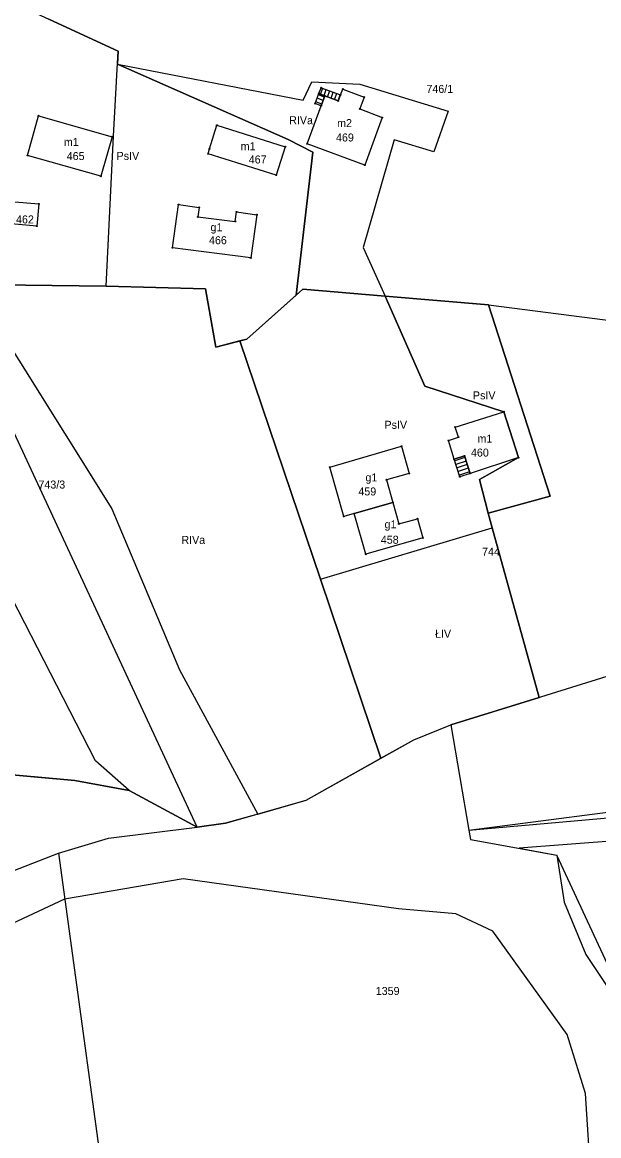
# Model space of a CAD drawing. Extents: x 7498273 to 7499989, y 5499795 to 5500810.
# Drawn here: x 7498588.9 to 7498697.1, y 5500193.5 to 5500402.3 of the extents above; entities that cross this region are included whole.
import ezdxf

# ---------------------------------------------------------------- set-up
doc = ezdxf.new("R2010")
doc.units = 0
for name, color, linetype in [('209-oznaczenie konturu klasyfikacyjnego', 7, 'Continuous'), ('211-numer działki ewidencyjnej', 7, 'Continuous'), ('217-kontur klasyfikacyjny', 7, 'Continuous'), ('218-kontur użytku gruntowego', 7, 'Continuous'), ('219-działka ewidencyjna', 7, 'Continuous'), ('312-budynek ewidencyjny', 7, 'Continuous'), ('312-oznaczenie budynku ewidencyjnego', 7, 'Continuous'), ('312-oznaczenie budynku ewidencyjnego-Atr117', 7, 'Continuous'), ('352-schody', 7, 'Continuous'), ('Punkt budynku', 7, 'Continuous')]:
    doc.layers.add(name, color=color, linetype=linetype)

# ---------------------------------------------------------------- blocks, each defined once
blk = doc.blocks.new('PUNKTBUD')
blk.add_circle((0, 0), 0.09)

msp = doc.modelspace()

# ---------------------------------------------------------------- linework, layer by layer
at = {"layer": '217-kontur klasyfikacyjny'}
for points in [[(7498606.9, 5500396.84), (7498593.88, 5500402.87)], [(7498606.76, 5500394.41), (7498606.9, 5500396.84)], [(7498638.84, 5500380.3), (7498606.76, 5500394.41)], [(7498606.76, 5500394.41), (7498641.62, 5500387.66)], [(7498641.62, 5500387.66), (7498643.28, 5500391.11)], [(7498643.28, 5500391.11), (7498652.24, 5500390.7)], [(7498652.24, 5500390.7), (7498668.87, 5500385.6)], [(7498668.87, 5500385.6), (7498666.18, 5500378.02)], [(7498643.47, 5500377.94), (7498638.84, 5500380.3)], [(7498658.73, 5500380.22), (7498652.9, 5500360.03)], [(7498666.18, 5500378.02), (7498658.73, 5500380.22)], [(7498640.34, 5500351.13), (7498643.47, 5500377.94)], [(7498652.9, 5500360.03), (7498657.01, 5500350.92)], [(7498579.32, 5500353.13), (7498604.68, 5500352.8)], [(7498579.32, 5500353.13), (7498605.75, 5500311.04)], [(7498604.68, 5500352.8), (7498623.33, 5500352.31)], [(7498623.33, 5500352.31), (7498625.26, 5500341.37)], [(7498631.03, 5500342.86), (7498640.34, 5500351.13)], [(7498640.34, 5500351.13), (7498641.57, 5500352.22)], [(7498641.57, 5500352.22), (7498657.01, 5500350.92)], [(7498657.01, 5500350.92), (7498676.4, 5500349.28)], [(7498664.46, 5500334.03), (7498657.01, 5500350.92)], [(7498676.4, 5500349.28), (7498687.99, 5500313.43)], [(7498625.26, 5500341.37), (7498629.74, 5500342.53)], [(7498629.74, 5500342.53), (7498631.03, 5500342.86)], [(7498644.86, 5500297.89), (7498629.74, 5500342.53)], [(7498679.3, 5500329.25), (7498664.46, 5500334.03)], [(7498682.05, 5500320.65), (7498679.3, 5500329.25)], [(7498674.7, 5500316.58), (7498682.05, 5500320.65)], [(7498676.35, 5500310.23), (7498674.7, 5500316.58)], [(7498687.99, 5500313.43), (7498676.35, 5500310.23)], [(7498605.75, 5500311.04), (7498618.44, 5500280.9)], [(7498676.35, 5500310.23), (7498677.12, 5500307.48)], [(7498644.86, 5500297.89), (7498677.12, 5500307.48)], [(7498677.12, 5500307.48), (7498685.92, 5500275.7)], [(7498656.24, 5500264.28), (7498644.86, 5500297.89)], [(7498602.66, 5500263.82), (7498586.95, 5500294.36)], [(7498618.44, 5500280.9), (7498633.11, 5500253.83)], [(7498685.92, 5500275.7), (7498669.36, 5500270.56)], [(7498662.43, 5500267.74), (7498669.36, 5500270.56)], [(7498669.36, 5500270.56), (7498672.71, 5500250.81)], [(7498656.24, 5500264.28), (7498662.43, 5500267.74)], [(7498598.77, 5500260.15), (7498565.56, 5500263.13)], [(7498608.96, 5500258.22), (7498602.66, 5500263.82)], [(7498642.2, 5500256.43), (7498656.24, 5500264.28)], [(7498608.96, 5500258.22), (7498598.77, 5500260.15)], [(7498621.71, 5500251.36), (7498608.96, 5500258.22)], [(7498633.11, 5500253.83), (7498642.2, 5500256.43)], [(7498672.71, 5500250.81), (7498717.23, 5500254.76)], [(7498633.11, 5500253.83), (7498627.05, 5500252.1)], [(7498605.1, 5500249.3), (7498621.71, 5500251.36)], [(7498627.05, 5500252.1), (7498621.71, 5500251.36)], [(7498719.84, 5500250.28), (7498682.16, 5500247.41)], [(7498595.68, 5500246.48), (7498605.1, 5500249.3)], [(7498567.27, 5500235.44), (7498595.68, 5500246.48)], [(7498682.16, 5500247.41), (7498689.24, 5500246.14)], [(7498689.24, 5500246.14), (7498690.63, 5500237.31)], [(7498619.14, 5500241.7), (7498596.86, 5500237.88)], [(7498659.5, 5500236.08), (7498619.14, 5500241.7)], [(7498596.86, 5500237.88), (7498585.09, 5500232.36)], [(7498670.28, 5500235.13), (7498659.5, 5500236.08)], [(7498690.63, 5500237.31), (7498694.7, 5500227.52)], [(7498677.22, 5500231.86), (7498670.28, 5500235.13)], [(7498691.19, 5500212.51), (7498677.22, 5500231.86)], [(7498694.7, 5500227.52), (7498705.34, 5500211.55)], [(7498694.6, 5500201.43), (7498691.19, 5500212.51)], [(7498695.67, 5500184.92), (7498694.6, 5500201.43)]]:
    msp.add_lwpolyline(points, dxfattribs=at)
at = {"layer": '218-kontur użytku gruntowego'}
for points in [[(7498593.88, 5500402.87), (7498606.9, 5500396.84)], [(7498606.9, 5500396.84), (7498606.76, 5500394.41)], [(7498606.76, 5500394.41), (7498641.62, 5500387.66)], [(7498606.76, 5500394.41), (7498638.84, 5500380.3)], [(7498641.62, 5500387.66), (7498643.28, 5500391.11)], [(7498643.28, 5500391.11), (7498652.24, 5500390.7)], [(7498652.24, 5500390.7), (7498668.87, 5500385.6)], [(7498668.87, 5500385.6), (7498666.18, 5500378.02)], [(7498638.84, 5500380.3), (7498643.47, 5500377.94)], [(7498658.73, 5500380.22), (7498652.9, 5500360.03)], [(7498666.18, 5500378.02), (7498658.73, 5500380.22)], [(7498643.47, 5500377.94), (7498640.34, 5500351.13)], [(7498652.9, 5500360.03), (7498657.01, 5500350.92)], [(7498579.32, 5500353.13), (7498605.75, 5500311.04)], [(7498604.68, 5500352.8), (7498579.32, 5500353.13)], [(7498623.33, 5500352.31), (7498604.68, 5500352.8)], [(7498625.26, 5500341.37), (7498623.33, 5500352.31)], [(7498640.34, 5500351.13), (7498631.03, 5500342.86)], [(7498641.57, 5500352.22), (7498640.34, 5500351.13)], [(7498657.01, 5500350.92), (7498641.57, 5500352.22)], [(7498657.01, 5500350.92), (7498664.46, 5500334.03)], [(7498676.4, 5500349.28), (7498657.01, 5500350.92)], [(7498687.99, 5500313.43), (7498676.4, 5500349.28)], [(7498629.74, 5500342.53), (7498625.26, 5500341.37)], [(7498631.03, 5500342.86), (7498629.74, 5500342.53)], [(7498629.74, 5500342.53), (7498644.86, 5500297.89)], [(7498664.46, 5500334.03), (7498679.3, 5500329.25)], [(7498679.3, 5500329.25), (7498682.05, 5500320.65)], [(7498682.05, 5500320.65), (7498674.7, 5500316.58)], [(7498674.7, 5500316.58), (7498676.35, 5500310.23)], [(7498676.35, 5500310.23), (7498687.99, 5500313.43)], [(7498605.75, 5500311.04), (7498618.44, 5500280.9)], [(7498677.12, 5500307.48), (7498676.35, 5500310.23)], [(7498644.86, 5500297.89), (7498677.12, 5500307.48)], [(7498685.92, 5500275.7), (7498677.12, 5500307.48)], [(7498644.86, 5500297.89), (7498656.24, 5500264.28)], [(7498602.66, 5500263.82), (7498586.95, 5500294.36)], [(7498618.44, 5500280.9), (7498633.11, 5500253.83)], [(7498669.36, 5500270.56), (7498685.92, 5500275.7)], [(7498662.43, 5500267.74), (7498669.36, 5500270.56)], [(7498669.36, 5500270.56), (7498672.71, 5500250.81)], [(7498656.24, 5500264.28), (7498662.43, 5500267.74)], [(7498565.56, 5500263.13), (7498598.77, 5500260.15)], [(7498608.96, 5500258.22), (7498602.66, 5500263.82)], [(7498642.2, 5500256.43), (7498656.24, 5500264.28)], [(7498598.77, 5500260.15), (7498608.96, 5500258.22)], [(7498621.71, 5500251.36), (7498608.96, 5500258.22)], [(7498633.11, 5500253.83), (7498642.2, 5500256.43)], [(7498672.71, 5500250.81), (7498717.23, 5500254.76)], [(7498633.11, 5500253.83), (7498627.05, 5500252.1)], [(7498605.1, 5500249.3), (7498621.71, 5500251.36)], [(7498627.05, 5500252.1), (7498621.71, 5500251.36)], [(7498719.84, 5500250.28), (7498682.16, 5500247.41)], [(7498595.68, 5500246.48), (7498605.1, 5500249.3)], [(7498567.27, 5500235.44), (7498595.68, 5500246.48)], [(7498682.16, 5500247.41), (7498689.24, 5500246.14)], [(7498689.24, 5500246.14), (7498690.63, 5500237.31)], [(7498619.14, 5500241.7), (7498596.86, 5500237.88)], [(7498659.5, 5500236.08), (7498619.14, 5500241.7)], [(7498596.86, 5500237.88), (7498585.09, 5500232.36)], [(7498670.28, 5500235.13), (7498659.5, 5500236.08)], [(7498690.63, 5500237.31), (7498694.7, 5500227.52)], [(7498677.22, 5500231.86), (7498670.28, 5500235.13)], [(7498691.19, 5500212.51), (7498677.22, 5500231.86)], [(7498694.7, 5500227.52), (7498705.34, 5500211.55)], [(7498694.6, 5500201.43), (7498691.19, 5500212.51)], [(7498695.67, 5500184.92), (7498694.6, 5500201.43)]]:
    msp.add_lwpolyline(points, dxfattribs=at)
at = {"layer": '219-działka ewidencyjna'}
for points in [[(7498567.09, 5500415.26), (7498606.9, 5500396.84)], [(7498606.01, 5500380.96), (7498606.9, 5500396.84)], [(7498604.68, 5500352.8), (7498606.01, 5500380.96)], [(7498574.39, 5500353.19), (7498604.68, 5500352.8)], [(7498621.71, 5500251.36), (7498574.39, 5500353.19)], [(7498623.33, 5500352.31), (7498604.68, 5500352.8)], [(7498623.33, 5500352.31), (7498625.26, 5500341.37)], [(7498631.03, 5500342.86), (7498641.57, 5500352.22)], [(7498641.57, 5500352.22), (7498676.4, 5500349.28)], [(7498676.4, 5500349.28), (7498720.2, 5500343.69)], [(7498625.26, 5500341.37), (7498631.03, 5500342.86)], [(7498669.36, 5500270.56), (7498716.61, 5500285.22)], [(7498662.43, 5500267.74), (7498669.36, 5500270.56)], [(7498669.36, 5500270.56), (7498672.71, 5500250.81)], [(7498642.2, 5500256.43), (7498662.43, 5500267.74)], [(7498557.81, 5500263.82), (7498598.77, 5500260.15)], [(7498608.96, 5500258.22), (7498598.77, 5500260.15)], [(7498608.96, 5500258.22), (7498621.71, 5500251.36)], [(7498627.05, 5500252.1), (7498642.2, 5500256.43)], [(7498672.71, 5500250.81), (7498711.32, 5500255.79)], [(7498605.1, 5500249.3), (7498621.71, 5500251.36)], [(7498621.71, 5500251.36), (7498627.05, 5500252.1)], [(7498672.71, 5500250.81), (7498673.03, 5500249.05)], [(7498595.68, 5500246.48), (7498605.1, 5500249.3)], [(7498673.03, 5500249.05), (7498689.24, 5500246.14)], [(7498567.27, 5500235.44), (7498595.68, 5500246.48)], [(7498595.68, 5500246.48), (7498606.29, 5500169.26)], [(7498714.83, 5500191.15), (7498689.24, 5500246.14)]]:
    msp.add_lwpolyline(points, dxfattribs=at)
at = {"layer": '312-budynek ewidencyjny'}
for points in [[(7498645.01, 5500386.62), (7498645.7, 5500388.48)], [(7498645.7, 5500388.48), (7498648.23, 5500387.54)], [(7498648.23, 5500387.54), (7498648.64, 5500388.67)], [(7498648.64, 5500388.67), (7498649.05, 5500389.75)], [(7498649.05, 5500389.75), (7498653.1, 5500388.25)], [(7498653.1, 5500388.25), (7498652.26, 5500386.04)], [(7498642.37, 5500379.51), (7498645.01, 5500386.62)], [(7498652.26, 5500386.04), (7498656.46, 5500384.42)], [(7498589.91, 5500377.33), (7498591.94, 5500384.77)], [(7498591.94, 5500384.77), (7498605.77, 5500380.83)], [(7498656.46, 5500384.42), (7498653.18, 5500375.5)], [(7498624.08, 5500378.58), (7498625.46, 5500382.98)], [(7498625.46, 5500382.98), (7498638.27, 5500378.96)], [(7498605.77, 5500380.83), (7498603.66, 5500373.41)], [(7498623.78, 5500377.63), (7498624.08, 5500378.58)], [(7498636.59, 5500373.62), (7498623.78, 5500377.63)], [(7498638.27, 5500378.96), (7498636.59, 5500373.62)], [(7498653.18, 5500375.5), (7498642.37, 5500379.51)], [(7498603.66, 5500373.41), (7498589.91, 5500377.33)], [(7498582.91, 5500369.02), (7498591.99, 5500368.23)], [(7498591.99, 5500368.23), (7498591.63, 5500364.06)], [(7498617.11, 5500360.02), (7498618.25, 5500368.12)], [(7498618.25, 5500368.12), (7498622.13, 5500367.57)], [(7498622.13, 5500367.57), (7498621.88, 5500365.79)], [(7498621.88, 5500365.79), (7498628.88, 5500364.96)], [(7498628.88, 5500364.96), (7498629.13, 5500366.74)], [(7498629.13, 5500366.74), (7498632.92, 5500366.21)], [(7498632.92, 5500366.21), (7498631.78, 5500358.09)], [(7498591.63, 5500364.06), (7498582.55, 5500364.85)], [(7498631.78, 5500358.09), (7498617.11, 5500360.02)], [(7498670.17, 5500326.39), (7498679.3, 5500329.25)], [(7498679.3, 5500329.25), (7498682.05, 5500320.65)], [(7498670.8, 5500324.49), (7498670.17, 5500326.39)], [(7498668.9, 5500323.86), (7498670.8, 5500324.49)], [(7498669.98, 5500320.35), (7498668.9, 5500323.86)], [(7498646.63, 5500318.85), (7498660.1, 5500322.78)], [(7498660.1, 5500322.78), (7498661.54, 5500317.71)], [(7498671.89, 5500320.97), (7498669.98, 5500320.35)], [(7498672.96, 5500317.68), (7498671.89, 5500320.97)], [(7498682.05, 5500320.65), (7498672.96, 5500317.68)], [(7498649.26, 5500309.62), (7498646.63, 5500318.85)], [(7498661.54, 5500317.71), (7498657.26, 5500316.5)], [(7498657.26, 5500316.5), (7498658.45, 5500312.27)], [(7498658.45, 5500312.27), (7498651.23, 5500310.18)], [(7498651.23, 5500310.18), (7498658.45, 5500312.27)], [(7498658.45, 5500312.27), (7498659.61, 5500308.22)], [(7498651.23, 5500310.18), (7498649.26, 5500309.62)], [(7498653.42, 5500302.54), (7498651.23, 5500310.18)], [(7498659.61, 5500308.22), (7498663.07, 5500309.2)], [(7498663.07, 5500309.2), (7498664.12, 5500305.61)], [(7498664.12, 5500305.61), (7498653.42, 5500302.54)]]:
    msp.add_lwpolyline(points, dxfattribs=at)
at = {"layer": '352-schody'}
for points in [[(7498645.01, 5500386.62), (7498643.88, 5500387.04), (7498644.57, 5500388.9), (7498645.7, 5500388.48)], [(7498645.01, 5500386.62), (7498643.88, 5500387.04), (7498644.57, 5500388.9), (7498645.7, 5500388.48)], [(7498644.99, 5500390.02), (7498648.64, 5500388.67), (7498648.23, 5500387.54), (7498645.7, 5500388.48), (7498644.57, 5500388.9)], [(7498644.99, 5500390.02), (7498648.64, 5500388.67), (7498648.23, 5500387.54), (7498645.7, 5500388.48), (7498644.57, 5500388.9)], [(7498671.06, 5500317.06), (7498669.98, 5500320.35), (7498671.89, 5500320.97), (7498672.96, 5500317.68)], [(7498671.06, 5500317.06), (7498669.98, 5500320.35), (7498671.89, 5500320.97), (7498672.96, 5500317.68)]]:
    msp.add_lwpolyline(points, close=True, dxfattribs=at)
for points in [[(7498645.375, 5500387.605), (7498644.245, 5500388.024)], [(7498645.619, 5500388.261), (7498644.489, 5500388.681)], [(7498644.903, 5500388.776), (7498645.318, 5500389.899)], [(7498645.559, 5500388.532), (7498645.975, 5500389.656)], [(7498646.215, 5500388.288), (7498646.631, 5500389.413)], [(7498646.872, 5500388.045), (7498647.288, 5500389.17)], [(7498647.528, 5500387.801), (7498647.944, 5500388.927)], [(7498648.184, 5500387.557), (7498648.601, 5500388.684)], [(7498645.132, 5500386.949), (7498644.002, 5500387.368)], [(7498671.985, 5500320.679), (7498670.078, 5500320.053)], [(7498672.201, 5500320.013), (7498670.296, 5500319.388)], [(7498672.418, 5500319.348), (7498670.514, 5500318.723)], [(7498672.634, 5500318.682), (7498670.733, 5500318.058)], [(7498672.851, 5500318.016), (7498670.951, 5500317.393)]]:
    msp.add_lwpolyline(points, dxfattribs=at)

# ---------------------------------------------------------------- block references
at = {"layer": 'Punkt budynku'}
for p in [(7498644.99, 5500390.02), (7498644.57, 5500388.9), (7498645.7, 5500388.48), (7498648.64, 5500388.67), (7498649.05, 5500389.75), (7498653.1, 5500388.25), (7498643.88, 5500387.04), (7498645.01, 5500386.62), (7498648.23, 5500387.54), (7498652.26, 5500386.04), (7498591.94, 5500384.77), (7498656.46, 5500384.42), (7498625.46, 5500382.98), (7498605.77, 5500380.83), (7498623.78, 5500377.63), (7498624.08, 5500378.58), (7498638.27, 5500378.96), (7498642.37, 5500379.51), (7498589.91, 5500377.33), (7498653.18, 5500375.5), (7498603.66, 5500373.41), (7498636.59, 5500373.62), (7498591.99, 5500368.23), (7498618.25, 5500368.12), (7498622.13, 5500367.57), (7498621.88, 5500365.79), (7498628.88, 5500364.96), (7498629.13, 5500366.74), (7498632.92, 5500366.21), (7498591.63, 5500364.06), (7498617.11, 5500360.02), (7498631.78, 5500358.09), (7498679.3, 5500329.25), (7498670.17, 5500326.39), (7498668.9, 5500323.86), (7498670.8, 5500324.49), (7498660.1, 5500322.78), (7498669.98, 5500320.35), (7498671.89, 5500320.97), (7498682.05, 5500320.65), (7498646.63, 5500318.85), (7498661.54, 5500317.71), (7498671.06, 5500317.06), (7498672.96, 5500317.68), (7498657.26, 5500316.5), (7498658.45, 5500312.27), (7498649.26, 5500309.62), (7498651.23, 5500310.18), (7498663.07, 5500309.2), (7498659.61, 5500308.22), (7498664.12, 5500305.61), (7498653.42, 5500302.54)]:
    msp.add_blockref('PUNKTBUD', p, dxfattribs=at)

# ---------------------------------------------------------------- texts
at = {"layer": '209-oznaczenie konturu klasyfikacyjnego'}
for s, p in [('RIVa', (7498639.01, 5500383.17)), ('PsIV', (7498606.62, 5500376.48)), ('PsIV', (7498673.5, 5500331.58)), ('PsIV', (7498656.9, 5500326.06)), ('RIVa', (7498618.78, 5500304.48)), ('ŁIV', (7498666.39, 5500286.88))]:
    msp.add_text(s, height=1.5, dxfattribs=at).set_placement(p)
at = {"layer": '211-numer działki ewidencyjnej'}
for s, p in [('746/1', (7498664.77, 5500389.04)), ('743/3', (7498591.95, 5500314.86)), ('744', (7498675.22, 5500302.28)), ('1359', (7498655.26, 5500219.91))]:
    msp.add_text(s, height=1.5, dxfattribs=at).set_placement(p)
at = {"layer": '312-oznaczenie budynku ewidencyjnego'}
for s, p in [('469', (7498647.8, 5500379.93)), ('465', (7498597.26, 5500376.45)), ('467', (7498631.42, 5500375.81)), ('462', (7498587.74, 5500364.57)), ('466', (7498623.96, 5500360.67)), ('460', (7498673.13, 5500320.85)), ('459', (7498652, 5500313.57)), ('458', (7498656.21, 5500304.51))]:
    msp.add_text(s, height=1.5, dxfattribs=at).set_placement(p)
at = {"layer": '312-oznaczenie budynku ewidencyjnego-Atr117'}
for s, p in [('m2', (7498648.006, 5500382.63)), ('m1', (7498596.715, 5500379.09)), ('m1', (7498629.905, 5500378.3)), ('g1', (7498624.249, 5500363.11)), ('m1', (7498674.355, 5500323.47)), ('g1', (7498653.319, 5500316.2)), ('g1', (7498656.909, 5500307.41))]:
    msp.add_text(s, height=1.5, dxfattribs=at).set_placement(p)

doc.saveas('drawing.dxf')
